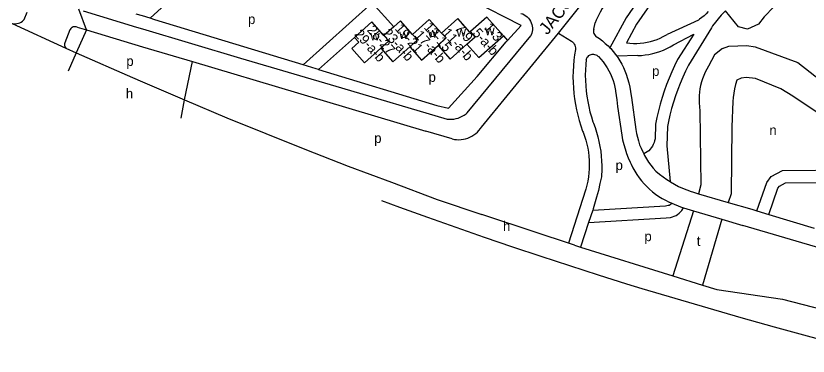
# Model space of a CAD drawing. Extents: x 159700 to 161346, y 381730 to 382922.
# Drawn here: x 160648.4 to 160971.8, y 381778.3 to 381917.2 of the extents above; entities that cross this region are included whole.
import ezdxf

# ---------------------------------------------------------------- set-up
doc = ezdxf.new("R2010")
doc.units = 0
for name, color, linetype in [('BLT_Basislijn', 7, 'Continuous'), ('BLT_Bebouwing', 7, 'Continuous'), ('BLT_Centroide', 7, 'Continuous'), ('BLT_Huisnummer_reeks', 7, 'Continuous'), ('BLT_Onderverdeling_panden', 7, 'Continuous'), ('BLT_Straatnaam', 7, 'Continuous'), ('BLT_Vlakafsluiter', 7, 'Continuous')]:
    doc.layers.add(name, color=color, linetype=linetype)

msp = doc.modelspace()

# ---------------------------------------------------------------- linework, layer by layer
at = {"layer": 'BLT_Basislijn'}
for p, q in [((160719.82, 381931.55), (160703.15, 381916.24)), ((160793.74, 381922.52), (160802.61, 381912.74)), ((160854.63, 381913.36), (160834.95, 381923.34)), ((160651.75, 381915.81), (160653.01, 381918.78)), ((160700, 381917.2), (160697.51, 381917.96)), ((160703.15, 381916.24), (160700, 381917.2)), ((160926.96, 381915.54), (160914.18, 381909.62)), ((160673.36, 381912.61), (160677.17, 381911.47)), ((160884.28, 381911.78), (160884.81, 381914.42)), ((160932.25, 381912.34), (160922.94, 381897.09)), ((160670.45, 381911.48), (160668.33, 381906.23)), ((160677.17, 381911.47), (160673.04, 381902.2)), ((160677.17, 381911.47), (160700, 381904.65)), ((160771.88, 381895.33), (160786.55, 381908.46)), ((160832.56, 381877.59), (160858.59, 381909.1)), ((160838.36, 381871.84), (160869.82, 381910.13)), ((160847.36, 381909.03), (160849.08, 381907.24)), ((160869.82, 381910.13), (160875.14, 381906.9)), ((160668.73, 381904.11), (160673.04, 381902.2)), ((160673.04, 381902.2), (160696.03, 381892.05)), ((160700, 381904.65), (160702.42, 381903.93)), ((160702.42, 381903.93), (160720.42, 381898.57)), ((160902.2, 381901), (160893.69, 381900.74)), ((160720.42, 381898.57), (160763.29, 381885.79)), ((160696.03, 381892.05), (160700, 381890.36)), ((160700, 381890.36), (160717.24, 381883)), ((160763.29, 381885.79), (160815.64, 381870.2)), ((160781.32, 381887.79), (160824.44, 381875.11)), ((160717.24, 381883), (160734.49, 381875.64)), ((160899.61, 381883.9), (160901.43, 381870.81)), ((160893.99, 381880.25), (160895.65, 381868.46)), ((160909.41, 381872.93), (160909.25, 381867.03)), ((160826.43, 381867), (160815.64, 381870.2)), ((160880.83, 381846.02), (160874, 381824.42)), ((160924.5, 381845.33), (160926.98, 381844.61)), ((160926.98, 381844.61), (160939.15, 381841.07)), ((160915.11, 381841.16), (160916.1, 381840.74)), ((160939.15, 381841.07), (160948.75, 381838.28)), ((160883.8, 381837.97), (160882.14, 381832.86)), ((160883.8, 381837.97), (160913.52, 381839.7)), ((160883.96, 381838.45), (160883.8, 381837.97)), ((160913.52, 381839.7), (160914.64, 381839.88)), ((160925.02, 381837.63), (160916.48, 381811.15)), ((160920.85, 381838.88), (160925.02, 381837.63)), ((160925.02, 381837.63), (160936.55, 381834.17)), ((160948.75, 381838.28), (160950.86, 381837.64)), ((160950.86, 381837.64), (160955.65, 381836.18)), ((160882.14, 381832.86), (160913.82, 381834.71)), ((160913.82, 381834.71), (160915.63, 381834.98)), ((160936.55, 381834.17), (160928.68, 381807.35)), ((160936.55, 381834.17), (160945.12, 381831.6)), ((160955.65, 381836.18), (160974.22, 381830.55)), ((160882.14, 381832.86), (160878.88, 381822.85)), ((161050.43, 381800.59), (160945.12, 381831.6)), ((160876.35, 381823.64), (160874, 381824.42)), ((160876.35, 381823.64), (160878.88, 381822.85)), ((160878.88, 381822.85), (160916.48, 381811.15)), ((160916.48, 381811.15), (160928.68, 381807.35))]:
    msp.add_line(p, q, dxfattribs=at)
for points in [[(160869.82, 381910.13), (160903.05, 381951.79), (160911.26, 381962.12), (160920.61, 381972.78), (160923.88, 381976.99), (160924.72, 381978.39), (160932.29, 381987.27), (160952.21, 382011.52), (160956.58, 382016.57), (160959.68, 382020.5), (160961.97, 382022.98), (160980.7, 382045.61), (160986.69, 382052.53), (161016.71, 382083.47)], [(160936.8, 381903.9), (160939.4, 381904.8), (160946.77, 381905.13), (160950.06, 381904.53), (160967.53, 381898.19), (160990.84, 381880.01), (161015.56, 381873.85), (161039.19, 381871.65), (161042.43, 381872.42), (161045.2, 381874.07), (161047.72, 381877.89), (161048.26, 381880.45), (161047.72, 381884.94), (161046.24, 381888.56), (161043.55, 381891.83), (161035.7, 381898.84), (161026.61, 381911.3), (161020.27, 381931.52), (161018.6, 381951.08), (161022.82, 381960.67), (161026.64, 381967.13), (161029.66, 381969.65), (161041.51, 381974.99)], [(160995.43, 381962.27), (160995.93, 381961.46), (160996.3, 381955.55), (160992, 381949.83), (160984.88, 381945.71), (160979.52, 381942.06), (160974.74, 381937.67), (160970.93, 381933.55), (160962.4, 381925.74), (160957.73, 381920.97), (160953.86, 381916.83), (160951.54, 381913.88), (160946.96, 381911.83), (160943.32, 381912.8), (160938.04, 381919.3)], [(160916.85, 381944.54), (160897.46, 381916.45), (160890.84, 381904.2)], [(160920.96, 381941.7), (160901.73, 381913.83), (160897.63, 381906.26)], [(160891.86, 381925.93), (160890.72, 381924.57), (160889.64, 381923.17), (160888.63, 381921.71), (160887.68, 381920.22), (160886.8, 381918.68), (160885.99, 381917.1), (160885.25, 381915.49), (160884.81, 381914.42)], [(160793.74, 381922.52), (160765.63, 381897.23)], [(160675.88, 381919.22), (160697.55, 381912.65), (160700, 381911.92)], [(160854.54, 381918.26), (160855.23, 381918.01), (160855.88, 381917.68), (160856.49, 381917.28), (160857.05, 381916.82), (160857.56, 381916.29), (160858.01, 381915.72), (160858.4, 381915.1), (160858.71, 381914.44), (160858.95, 381913.75), (160859.11, 381913.04), (160859.2, 381912.32), (160859.2, 381911.59), (160859.13, 381910.86), (160858.97, 381910.15), (160858.74, 381909.46), (160858.59, 381909.1)], [(160930.97, 381918.99), (160930.16, 381918.11), (160929.3, 381917.3), (160928.39, 381916.54), (160927.43, 381915.85), (160926.96, 381915.54)], [(160938.04, 381919.3), (160937.57, 381918.84), (160936.28, 381917.48), (160935.05, 381916.07), (160933.88, 381914.61), (160932.77, 381913.11), (160932.25, 381912.34)], [(160646.91, 381914.06), (160647.55, 381914.04), (160648.16, 381914.01), (160648.78, 381914.07), (160649.38, 381914.21), (160649.96, 381914.42), (160650.5, 381914.71), (160651.01, 381915.06), (160651.46, 381915.48), (160651.75, 381915.81)], [(160765.63, 381897.23), (160705.1, 381915.63), (160703.15, 381916.24)], [(160673.36, 381912.61), (160672.97, 381912.75), (160672.56, 381912.82), (160672.15, 381912.8), (160671.75, 381912.71), (160671.37, 381912.54), (160671.04, 381912.31), (160670.75, 381912.01), (160670.53, 381911.66), (160670.45, 381911.48)], [(160700, 381911.92), (160740.09, 381899.95), (160781.32, 381887.79)], [(160849.08, 381907.24), (160854.63, 381913.36)], [(160884.28, 381911.78), (160884.18, 381911.33), (160884.15, 381910.87), (160884.2, 381910.41), (160884.33, 381909.97), (160884.54, 381909.56), (160884.81, 381909.19), (160885.14, 381908.87), (160885.23, 381908.8)], [(160885.23, 381908.8), (160886.52, 381907.93), (160887.76, 381907), (160888.96, 381906.01), (160890.1, 381904.96), (160890.84, 381904.2)], [(160897.63, 381906.26), (160899.03, 381906.09), (160900.43, 381906.01), (160901.84, 381906), (160903.24, 381906.07), (160904.64, 381906.22), (160906.02, 381906.45), (160907.39, 381906.76), (160908.75, 381907.14), (160910.07, 381907.61), (160911.37, 381908.14), (160912.64, 381908.75), (160913.87, 381909.43), (160914.18, 381909.62)], [(160916.79, 381905.36), (160925.14, 381909.71), (160918.49, 381899.37)], [(160668.33, 381906.23), (160668.21, 381905.87), (160668.16, 381905.5), (160668.2, 381905.13), (160668.32, 381904.77), (160668.51, 381904.45), (160668.73, 381904.11)], [(160771.88, 381895.33), (160820.16, 381880.64), (160825, 381879.5), (160836.72, 381892.43), (160848.53, 381906.63), (160849.08, 381907.24)], [(160875.14, 381906.9), (160875.57, 381906.57), (160875.94, 381906.18), (160876.25, 381905.74), (160876.49, 381905.25), (160876.66, 381904.74), (160876.75, 381904.21), (160876.77, 381903.67), (160876.76, 381903.55)], [(160902.2, 381901), (160903.74, 381901.09), (160905.27, 381901.26), (160906.79, 381901.51), (160908.3, 381901.83), (160909.79, 381902.23), (160911.25, 381902.71), (160912.69, 381903.27), (160914.1, 381903.9), (160915.47, 381904.6), (160916.79, 381905.36)], [(160876.76, 381903.55), (160876.4, 381901.33), (160876.12, 381899.09), (160875.92, 381896.84), (160875.8, 381894.58), (160875.75, 381892.33), (160875.79, 381890.07), (160875.91, 381887.81), (160876.11, 381885.56), (160876.39, 381883.32), (160876.75, 381881.09), (160877.18, 381878.88), (160877.7, 381876.68), (160878.29, 381874.5), (160878.96, 381872.35), (160879.7, 381870.21), (160879.89, 381869.72)], [(160890.84, 381904.2), (160891.18, 381903.85), (160892.21, 381902.68), (160893.17, 381901.47), (160893.69, 381900.74)], [(160936.8, 381903.9), (160933.57, 381901.27), (160931.09, 381896.66)], [(160881.19, 381899.47), (160880.98, 381897.33), (160880.85, 381895.17), (160880.8, 381893.01), (160880.83, 381890.86), (160880.95, 381888.7), (160881.14, 381886.55), (160881.41, 381884.41), (160881.76, 381882.28), (160882.18, 381880.17), (160882.69, 381878.07), (160883.27, 381875.99), (160883.93, 381873.94), (160884.09, 381873.49)], [(160881.19, 381899.47), (160881.37, 381899.92), (160881.61, 381900.34), (160881.93, 381900.7), (160882.29, 381901.01), (160882.71, 381901.26), (160883.16, 381901.43), (160883.63, 381901.53), (160884.11, 381901.54), (160884.59, 381901.48), (160885.05, 381901.34), (160885.48, 381901.12), (160885.87, 381900.84), (160886.13, 381900.58)], [(160886.13, 381900.58), (160887.11, 381899.52), (160888.02, 381898.42), (160888.87, 381897.26), (160889.66, 381896.06), (160890.38, 381894.82), (160891.02, 381893.54), (160891.6, 381892.23), (160892.1, 381890.88), (160892.52, 381889.51), (160892.87, 381888.12), (160893.14, 381886.71), (160893.17, 381886.54)], [(160893.69, 381900.74), (160894.07, 381900.2), (160894.91, 381898.9), (160895.67, 381897.55), (160896.37, 381896.16), (160896.99, 381894.74), (160897.51, 381893.37)], [(160918.49, 381899.37), (160917.25, 381896.87), (160916.08, 381894.34), (160914.99, 381891.77), (160913.97, 381889.17), (160913.02, 381886.55), (160912.15, 381883.89), (160911.35, 381881.22), (160910.64, 381878.52), (160910, 381875.8), (160909.43, 381873.07), (160909.41, 381872.93)], [(160771.88, 381895.33), (160770.99, 381895.6), (160765.63, 381897.23)], [(160922.94, 381897.09), (160921.73, 381894.65), (160920.6, 381892.18), (160919.54, 381889.68), (160918.55, 381887.15), (160917.63, 381884.58), (160916.8, 381882), (160916.03, 381879.39), (160915.35, 381876.75), (160914.74, 381874.1), (160914.32, 381872)], [(160931.09, 381896.66), (160930.37, 381895.45), (160929.72, 381894.19), (160929.14, 381892.91), (160928.63, 381891.59), (160928.2, 381890.24), (160927.85, 381888.87), (160927.57, 381887.48), (160927.37, 381886.08), (160927.25, 381884.68), (160927.21, 381883.26), (160927.26, 381881.76)], [(160897.51, 381893.37), (160898.07, 381891.65), (160898.55, 381889.91), (160898.96, 381888.15), (160899.29, 381886.38), (160899.53, 381884.59), (160899.61, 381883.9)], [(160942.66, 381890.99), (160942.16, 381889.25), (160941.74, 381887.49), (160941.4, 381885.72), (160941.15, 381883.93), (160940.98, 381882.33)], [(160974.98, 381878.09), (160965.47, 381884.42), (160960.59, 381887.49), (160950.23, 381891.62), (160946.44, 381892.01), (160944.36, 381891.79), (160942.66, 381890.99)], [(160893.17, 381886.54), (160893.66, 381883), (160893.99, 381880.25)], [(160927.26, 381881.76), (160927.51, 381878.51), (160927.95, 381848.2), (160926.98, 381844.61)], [(160940.98, 381882.33), (160940.64, 381871.92), (160940.29, 381844.57), (160939.15, 381841.07)], [(160824.44, 381875.11), (160825.35, 381875.04), (160826.25, 381875.04), (160827.15, 381875.12), (160828.05, 381875.28), (160828.92, 381875.52), (160829.77, 381875.84), (160830.59, 381876.23), (160831.37, 381876.69), (160832.1, 381877.22), (160832.56, 381877.59)], [(160950.86, 381837.64), (160954.89, 381849.21), (160956.67, 381851.6), (160961.26, 381854.08), (160988.36, 381854.38), (160998.92, 381855.12), (161008.1, 381853.36), (161014.84, 381849.46), (161024.52, 381839.65), (161032.45, 381836.35), (161040.71, 381835.31), (161047.69, 381835.58), (161053.25, 381837.85), (161059.08, 381842.46), (161063.27, 381847.4), (161066.44, 381854.86), (161071.53, 381867.75), (161076.12, 381876.41)], [(160734.49, 381875.64), (160766.37, 381862.78), (160784.02, 381855.93), (160801.73, 381849.27)], [(160884.09, 381873.49), (160884.78, 381871.62), (160885.39, 381869.73), (160885.93, 381867.82), (160886.38, 381865.89), (160886.76, 381863.93), (160887.07, 381861.97), (160887.29, 381860), (160887.43, 381858.01), (160887.49, 381856.03), (160887.48, 381854.04), (160887.38, 381852.05), (160887.34, 381851.55)], [(160826.43, 381867), (160827.34, 381866.81), (160828.26, 381866.7), (160829.19, 381866.66), (160830.12, 381866.71), (160831.05, 381866.84), (160831.95, 381867.04), (160832.84, 381867.32), (160833.7, 381867.68), (160834.53, 381868.11), (160835.31, 381868.61), (160836.05, 381869.17), (160836.74, 381869.8), (160837.37, 381870.48), (160837.95, 381871.22), (160838.36, 381871.84)], [(160879.89, 381869.72), (160880.48, 381868.14), (160880.99, 381866.53), (160881.42, 381864.9), (160881.78, 381863.24), (160882.06, 381861.58), (160882.26, 381859.9), (160882.38, 381858.22), (160882.42, 381856.53), (160882.38, 381854.84), (160882.26, 381853.16), (160882.06, 381851.48), (160881.78, 381849.81), (160881.42, 381848.16), (160880.98, 381846.53), (160880.83, 381846.02)], [(160901.43, 381870.81), (160901.7, 381869.24), (160902.05, 381867.68), (160902.48, 381866.15), (160902.98, 381864.64), (160903.56, 381863.16), (160904.21, 381861.71), (160904.64, 381860.88)], [(160914.32, 381872), (160914.08, 381864.21), (160915.38, 381849.55)], [(160955.65, 381836.18), (160959.36, 381846.84), (160960.02, 381847.73), (160962.55, 381849.1), (160988.56, 381849.38), (160998.62, 381850.08), (161006.33, 381848.61), (161011.76, 381845.47), (161021.67, 381835.42), (161031.16, 381831.47), (161040.49, 381830.3), (161048.76, 381830.62), (161055.8, 381833.49), (161062.57, 381838.85), (161067.57, 381844.75), (161071.06, 381852.97), (161076.08, 381865.66), (161078.26, 381869.77)], [(160895.65, 381868.46), (160896.03, 381866.58), (160896.49, 381864.72), (160897.03, 381862.88), (160897.64, 381861.07), (160898.33, 381859.28), (160899.09, 381857.52), (160899.52, 381856.62)], [(160909.25, 381867.03), (160909.1, 381866.24), (160908.87, 381865.48), (160908.56, 381864.74), (160908.18, 381864.03), (160907.74, 381863.37), (160907.23, 381862.75), (160906.66, 381862.19), (160906.04, 381861.69), (160905.37, 381861.25), (160904.64, 381860.88)], [(160904.64, 381860.88), (160904.93, 381860.29), (160905.73, 381858.91), (160906.59, 381857.57), (160907.52, 381856.28), (160908.52, 381855.04), (160909.57, 381853.84), (160909.64, 381853.77)], [(160899.52, 381856.62), (160900.22, 381855.2), (160901, 381853.81), (160901.85, 381852.46), (160902.76, 381851.16), (160903.74, 381849.9), (160904.78, 381848.7), (160905.88, 381847.55), (160907.03, 381846.45), (160908.24, 381845.42), (160909.5, 381844.45), (160910.81, 381843.54), (160912.16, 381842.7), (160913.55, 381841.93), (160914.98, 381841.22), (160915.11, 381841.16)], [(160909.64, 381853.77), (160911.06, 381852.58), (160912.53, 381851.46), (160914.05, 381850.4), (160915.38, 381849.55)], [(160887.34, 381851.55), (160886.77, 381848.74), (160886.12, 381845.95), (160885.39, 381843.17), (160884.58, 381840.42), (160883.96, 381838.45)], [(160801.73, 381849.27), (160820.39, 381842.27), (160838.56, 381836.14)], [(160915.38, 381849.55), (160915.61, 381849.41), (160917.21, 381848.48), (160918.85, 381847.63), (160920.52, 381846.85), (160922.23, 381846.14), (160923.96, 381845.51), (160924.5, 381845.33)], [(160797.58, 381841.9), (160804.91, 381839.19), (160816.41, 381835.01), (160827.94, 381830.91), (160839.5, 381826.88), (160851.08, 381822.93), (160862.69, 381819.06), (160874.33, 381815.26), (160885.98, 381811.54), (160897.67, 381807.89), (160903.93, 381805.97)], [(160914.64, 381839.88), (160915.08, 381840.01), (160915.49, 381840.22), (160915.86, 381840.49), (160916.1, 381840.74)], [(160916.1, 381840.74), (160919.61, 381839.25), (160920.85, 381838.88)], [(160915.63, 381834.98), (160916.39, 381835.18), (160917.12, 381835.45), (160917.82, 381835.79), (160918.48, 381836.2), (160919.1, 381836.68), (160919.66, 381837.22), (160920.17, 381837.82), (160920.61, 381838.46), (160920.85, 381838.88)], [(160874, 381824.42), (160861.11, 381828.68), (160838.56, 381836.14)], [(160903.93, 381805.97), (160917.38, 381801.94), (160930.84, 381797.98), (160944.33, 381794.1), (160957.84, 381790.29), (160971.38, 381786.56), (160984.93, 381782.91), (160998.51, 381779.34), (161002.5, 381778.3)], [(160928.68, 381807.35), (160934.46, 381805.55), (160961.22, 381801.62), (161018.11, 381786.84)]]:
    msp.add_lwpolyline(points, dxfattribs=at)
at = {"layer": 'BLT_Bebouwing'}
for p, q in [((160793.68, 381914.77), (160786.55, 381908.46)), ((160798.61, 381909.2), (160793.68, 381914.77))]:
    msp.add_line(p, q, dxfattribs=at)
for points in [[(160810.3, 381909.68), (160805.4, 381915.22), (160802.61, 381912.74)], [(160822.14, 381910.21), (160822.05, 381910.12), (160817.1, 381915.7), (160810.3, 381909.68)], [(160833.88, 381910.8), (160833.7, 381910.64), (160828.83, 381916.13), (160822.14, 381910.21)], [(160847.36, 381909.03), (160840.55, 381916.71), (160833.88, 381910.8)], [(160802.61, 381912.74), (160798.61, 381909.2)], [(160786.55, 381908.46), (160788.32, 381906.46), (160785.46, 381903.93), (160790.61, 381898.11), (160797.35, 381904.09)], [(160832.49, 381905.71), (160837.38, 381900.19), (160847.36, 381909.03)], [(160809.14, 381904.6), (160813.92, 381899.21), (160820.69, 381905.2)], [(160820.69, 381905.2), (160825.62, 381899.62), (160832.49, 381905.71)], [(160797.35, 381904.09), (160802.28, 381898.52), (160809.14, 381904.6)]]:
    msp.add_lwpolyline(points, dxfattribs=at)
at = {"layer": 'BLT_Onderverdeling_panden'}
for p, q in [((160800.58, 381907.06), (160798.61, 381909.2)), ((160812.3, 381907.51), (160810.3, 381909.68)), ((160797.35, 381904.09), (160800.58, 381907.06)), ((160809.14, 381904.6), (160812.3, 381907.51))]:
    msp.add_line(p, q, dxfattribs=at)
for points in [[(160820.69, 381905.2), (160823.97, 381908.22), (160822.14, 381910.21)], [(160832.49, 381905.71), (160835.78, 381908.73), (160833.88, 381910.8)]]:
    msp.add_lwpolyline(points, dxfattribs=at)
at = {"layer": 'BLT_Vlakafsluiter'}
for p, q in [((160677.17, 381911.47), (160674.05, 381919.99)), ((160646.91, 381914.06), (160668.73, 381904.11)), ((160673.04, 381902.2), (160669.66, 381894.65)), ((160717.24, 381883), (160720.42, 381898.57)), ((160715.89, 381875.46), (160717.24, 381883))]:
    msp.add_line(p, q, dxfattribs=at)

# ---------------------------------------------------------------- texts
at = {"layer": 'BLT_Centroide'}
for s, p in [('p', (160743.13, 381913.88)), ('w', (160828.23, 381908.77)), ('w', (160839.92, 381909.3)), ('w', (160793.02, 381907.22)), ('w', (160804.83, 381907.75)), ('w', (160816.56, 381908.38)), ('p', (160693.46, 381896.79)), ('p', (160908.06, 381892.72)), ('p', (160816.82, 381890.29)), ('h', (160693.26, 381883.51)), ('n', (160955.93, 381868.58)), ('p', (160794.64, 381865.33)), ('p', (160893.16, 381854.28)), ('h', (160847.2, 381829.42)), ('p', (160904.92, 381825.24)), ('t', (160926.28, 381823.32))]:
    msp.add_text(s, height=4, dxfattribs=at).set_placement(p)
at = {"layer": 'BLT_Huisnummer_reeks'}
for s, rotation, p in [('29-a-b', 311.5269, (160786.28, 381909.58)), ('25-27', 311.5269, (160791.47, 381911.26)), ('23-a-b', 311.5324, (160797.88, 381909.93)), ('19-21', 311.5324, (160802.83, 381911.87)), ('13-15', 311.5292, (160814.65, 381912.41)), ('11-a-b', 311.5333, (160822.15, 381910.09)), ('7-9', 311.5333, (160827.19, 381911.93)), ('5-a-b', 311.5296, (160834.53, 381910.04)), ('1-3', 311.5296, (160839.26, 381912.23)), ('17-a-b', 311.5292, (160810.88, 381909.13))]:
    msp.add_text(s, height=4, rotation=rotation, dxfattribs=at).set_placement(p)
at = {"layer": 'BLT_Straatnaam'}
msp.add_text('JACOB VAN MAERLANTLAAN', height=4.9999, rotation=51.0994, dxfattribs=at).set_placement((160865.29, 381909.18))

doc.saveas('drawing.dxf')
